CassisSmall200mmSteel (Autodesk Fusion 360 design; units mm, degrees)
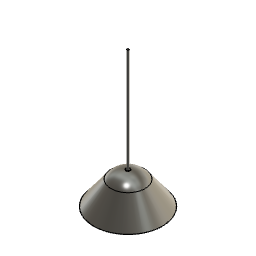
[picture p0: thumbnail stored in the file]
sketch "Sketch1" plane through (0, 0, 0) normal (0, 1, 0) x axis (1, 0, 0)
  line L1 (-5, -92) -> (0, -92)
  line L2 (-49, -69.2459) -> (-100, 0)
  line L3 (0, 0) -> (0, -92)
  line L4 (-100, 0) -> (0, 0)
  arc A1 centre (-2.909, -34.0377) radius 58 clockwise from (-5, -92) to (-49, -69.2459)
  point P1 (0, 0)
  point P4 (-100, 0)
  point P2 (0, -92)
  point P7 (0, 0)
  point P3 (-5, -92)
  point P5 (-49, -69.2459)
  horizontal L1
  horizontal P1 P4
  vertical P1 P2
  coincident P1 P7
  dimension "d1" distance P2 P3 = 5
  dimension "d2" distance P1 L1 = 92
  dimension "d3" distance P1 P4 = 100
  dimension "d4" radius A1 = 58
  dimension "d6" distance P4 P5 = 86
  dimension "d7" distance P1 P5 = 49
revolve "Revolve1" sketch "Sketch1" AlongAngle 360
shell "Shell1" innerThickness 1.5
fillet "Fillet1" radius 0.5
sketch "Sketch2" plane through (0, 0, 0) normal (0, 1, 0) x axis (1, 0, 0)
  line L1 (-32.2676, -70) -> (0, -70)
  point P1 (0, 0)
  horizontal L1
  dimension "d14" distance P1 L1 = 70
work_plane "WorkPlane1" AlongDistance 70
sketch "Sketch4" plane through (0, 0, 70) normal (0, 0, 1) x axis (1, 0, 0)
  circle C1 centre (0, 0) radius 43.7102
  point P1 (0, 0)
  point P2 (0, 0)
  coincident P1 P2
extrude "Extrude2" new body sketch "Sketch4" against normal blind 12 taper -20
sketch "Sketch5" plane through (0, 0, 58) normal (0, 0, -1) x axis (1, 0, 0)
  circle C1 centre (0, 0) radius 39.3425
  circle C2 centre (0, 0) radius 35.3425
  point P1 (0, 0)
  point P3 (0, 0)
  coincident P1 P3
  dimension "d19" distance C1 C2 = 4
extrude "Extrude3" cut sketch "Sketch5" profile of C2 against normal blind 10
extrude "Extrude4" new body of existing geometry blind 20
work_plane "WorkPlane2" AlongDistance -5
split "Split1"
fillet "Fillet2" radius 0.1
fillet "Fillet3" radius 0.4
sketch "Sketch6" plane through (0, 0, 92) normal (0, 0, 1) x axis (-1, 0, 0)
  circle C1 centre (0, 0) radius 5
  circle C2 centre (0, 0) radius 6
  point P1 (0, 0)
  point P3 (0, 0)
  coincident P1 P3
  dimension "d29" diameter C2 = 12
extrude "Extrude5" new body sketch "Sketch6" along normal blind 1.5
extrude "Extrude6" cut of existing geometry blind -1.5
sketch "Sketch7" plane through (0, 0, 70) normal (0, 0, 1) x axis (-1, 0, 0)
  circle C1 centre (0, 0) radius 43.7102
  circle C2 centre (0, 0) radius 3
  point P1 (0, 0)
  point P3 (0, 0)
  coincident P1 P3
  dimension "d34" diameter C2 = 6
extrude "Extrude7" new body sketch "Sketch7" profile of C2 along normal blind 323
fillet "Fillet4" radius 0.2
